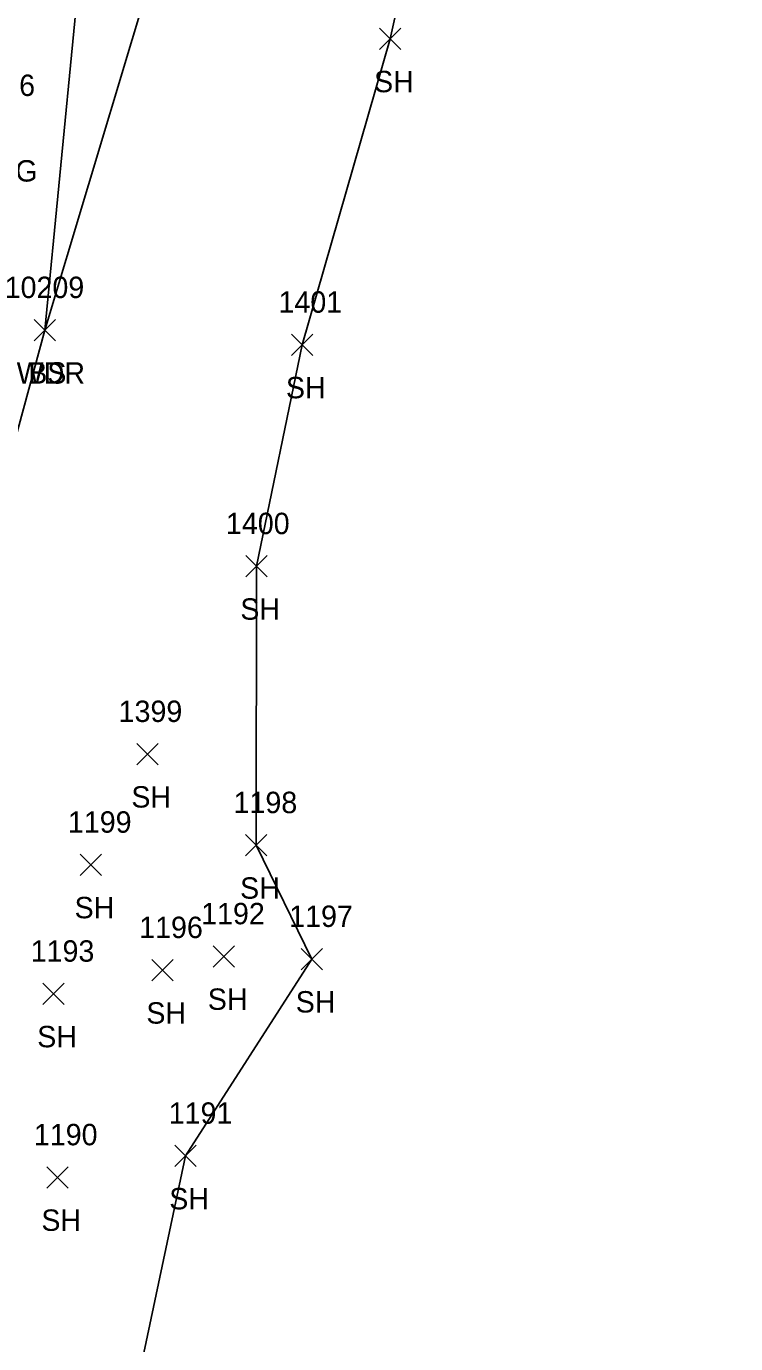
# Model space of a CAD drawing. Extents: x 1651685 to 1653558, y 889533 to 891085.
# Drawn here: x 1652767.1 to 1652833.4, y 890214.6 to 890337.8 of the extents above; entities that cross this region are included whole.
import ezdxf

# ---------------------------------------------------------------- set-up
doc = ezdxf.new("R2010")
doc.units = 0
for name, color, linetype in [('L_A', 7, 'Continuous'), ('L_I', 7, 'Continuous'), ('L_TIC', 7, 'Continuous'), ('LAWA', 7, 'Continuous'), ('LELB', 7, 'Continuous'), ('LSOGP', 7, 'Continuous'), ('R_A', 7, 'Continuous'), ('R_I', 7, 'Continuous')]:
    doc.layers.add(name, color=color, linetype=linetype)

msp = doc.modelspace()

# ---------------------------------------------------------------- linework, layer by layer
at = {"layer": 'L_TIC'}
for points in [[(1652800.11, 890335.6), (1652802.11, 890337.6)], [(1652802.11, 890335.6), (1652800.11, 890337.6)], [(1652767.84, 890308.36), (1652769.84, 890310.36)], [(1652769.84, 890308.36), (1652767.84, 890310.36)], [(1652767.84, 890308.36), (1652769.84, 890310.36)], [(1652769.84, 890308.36), (1652767.84, 890310.36)], [(1652791.87, 890306.99), (1652793.87, 890308.99)], [(1652793.87, 890306.99), (1652791.87, 890308.99)], [(1652787.61, 890286.29), (1652789.61, 890288.29)], [(1652789.61, 890286.29), (1652787.61, 890288.29)], [(1652777.43, 890268.73), (1652779.43, 890270.73)], [(1652779.43, 890268.73), (1652777.43, 890270.73)], [(1652787.59, 890260.21), (1652789.59, 890262.21)], [(1652789.59, 890260.21), (1652787.59, 890262.21)], [(1652772.12, 890258.38), (1652774.12, 890260.38)], [(1652774.12, 890258.38), (1652772.12, 890260.38)], [(1652784.57, 890249.82), (1652786.57, 890251.82)], [(1652786.57, 890249.82), (1652784.57, 890251.82)], [(1652792.79, 890249.57), (1652794.79, 890251.57)], [(1652794.79, 890249.57), (1652792.79, 890251.57)], [(1652778.83, 890248.53), (1652780.83, 890250.53)], [(1652780.83, 890248.53), (1652778.83, 890250.53)], [(1652768.64, 890246.32), (1652770.64, 890248.32)], [(1652770.64, 890246.32), (1652768.64, 890248.32)], [(1652780.97, 890231.17), (1652782.97, 890233.17)], [(1652782.97, 890231.17), (1652780.97, 890233.17)], [(1652769.02, 890229.16), (1652771.02, 890231.16)], [(1652771.02, 890229.16), (1652769.02, 890231.16)]]:
    msp.add_lwpolyline(points, dxfattribs=at)
at = {"layer": 'LAWA'}
msp.add_lwpolyline([(1652733.24, 890255.05), (1652739.87, 890255.53), (1652757.33, 890267.07), (1652768.84, 890309.36), (1652781.07, 890350.15), (1652797.71, 890393.69), (1652815.71, 890436.04), (1652825.05, 890456.62), (1652833.35, 890477.68), (1652833.39, 890492.3)], dxfattribs=at)
at = {"layer": 'LELB'}
msp.add_lwpolyline([(1652768.84, 890309.36), (1652773.05, 890352.75), (1652787.7, 890398.23), (1652803.19, 890441), (1652820.95, 890497.33)], dxfattribs=at)
at = {"layer": 'LSOGP'}
msp.add_lwpolyline([(1652776.24, 890205.05), (1652781.97, 890232.17), (1652793.79, 890250.57), (1652788.59, 890261.21), (1652788.61, 890287.29), (1652792.87, 890307.99), (1652801.11, 890336.6), (1652806.65, 890361.62)], dxfattribs=at)

# ---------------------------------------------------------------- texts
at = {"layer": 'L_A'}
for s, p in [('SH', (1652799.6, 890331.6)), ('WDR', (1652766.2, 890304.36)), ('BS', (1652767.28, 890304.36)), ('SH', (1652791.36, 890302.99)), ('SH', (1652787.1, 890282.29)), ('SH', (1652776.92, 890264.73)), ('SH', (1652787.08, 890256.21)), ('SH', (1652771.61, 890254.38)), ('SH', (1652784.06, 890245.82)), ('SH', (1652792.28, 890245.57)), ('SH', (1652778.32, 890244.53)), ('SH', (1652768.12, 890242.32)), ('SH', (1652780.46, 890227.17)), ('SH', (1652768.51, 890225.16))]:
    msp.add_text(s, height=2, dxfattribs=at).set_placement(p)
at = {"layer": 'L_I'}
for s, p in [('10209', (1652765.08, 890312.36)), ('10209', (1652765.08, 890312.36)), ('1401', (1652790.67, 890310.99)), ('1400', (1652785.76, 890290.29)), ('1399', (1652775.73, 890272.73)), ('1198', (1652786.47, 890264.21)), ('1199', (1652770.99, 890262.38)), ('1192', (1652783.44, 890253.82)), ('1196', (1652777.65, 890252.53)), ('1197', (1652791.67, 890253.57)), ('1193', (1652767.51, 890250.32)), ('1191', (1652780.41, 890235.17)), ('1190', (1652767.81, 890233.16))]:
    msp.add_text(s, height=2, dxfattribs=at).set_placement(p)
at = {"layer": 'R_A'}
msp.add_text('DRG', height=2, dxfattribs=at).set_placement((1652762.21, 890323.25))
at = {"layer": 'R_I'}
msp.add_text('1376', height=2, dxfattribs=at).set_placement((1652761.97, 890331.25))

doc.saveas('drawing.dxf')
